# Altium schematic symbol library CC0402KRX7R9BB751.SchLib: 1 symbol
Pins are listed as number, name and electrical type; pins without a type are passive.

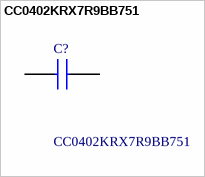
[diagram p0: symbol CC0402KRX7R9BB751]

## CC0402KRX7R9BB751
designator C?
Multilayer Ceramic Capacitors MLCC - SMD/SMT 750pF 50V 10% 0402 Case Size; Manufacturer_Name: Yageo Group; Geometry.Height: 0.55mm
footprint CAPC1005X55N
pins: 1, 2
